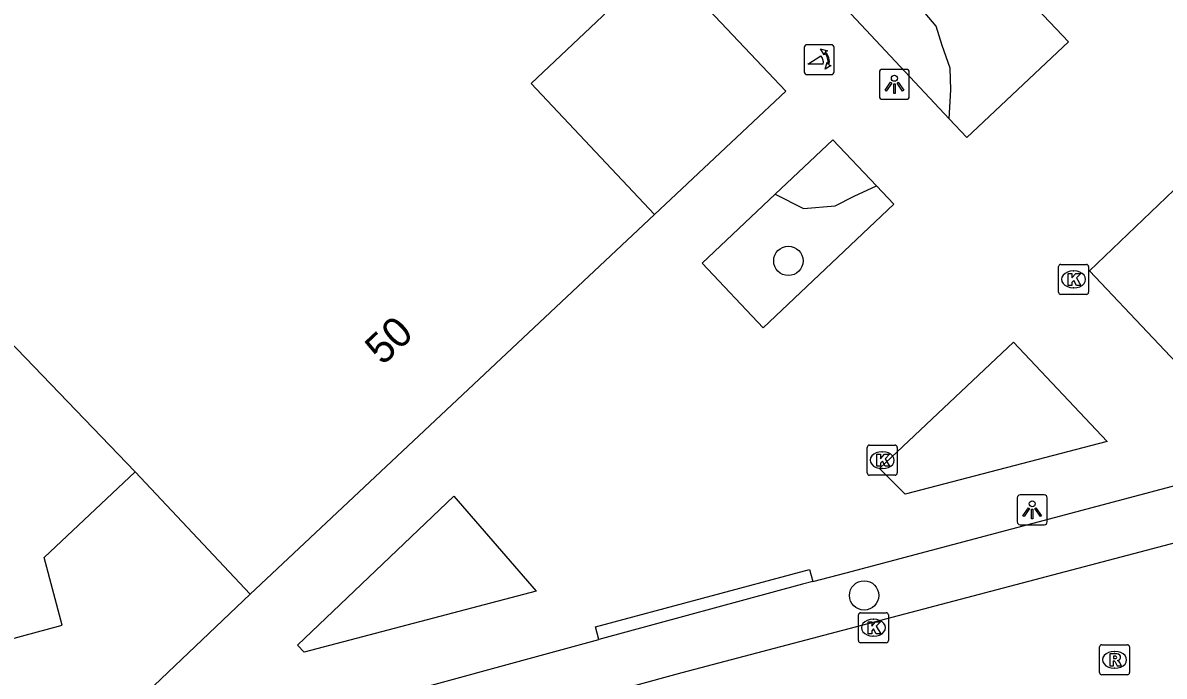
# Model space of a CAD drawing. Extents: x 162542 to 163144, y 380786 to 381511.
# Drawn here: x 162917.88 to 162955.91, y 381179.97 to 381201.72 of the extents above; entities that cross this region are included whole.
import ezdxf

# ---------------------------------------------------------------- set-up
doc = ezdxf.new("R2010")
doc.units = 0
for name, color, linetype in [('IMGEO_Boom', 7, 'Continuous'), ('IMGEO_Groenvoorziening', 7, 'Continuous'), ('IMGEO_Hek', 7, 'Continuous'), ('IMGEO_Kolk', 7, 'Continuous'), ('IMGEO_Lichtpunt', 7, 'Continuous'), ('IMGEO_Pand', 7, 'Continuous'), ('IMGEO_Pand_nummerreeks', 7, 'Continuous'), ('IMGEO_Poller', 7, 'Continuous'), ('IMGEO_Rijbaan_lokaal_open', 7, 'Continuous'), ('IMGEO_Rioolput', 7, 'Continuous'), ('IMGEO_Voetpad_open', 7, 'Continuous')]:
    doc.layers.add(name, color=color, linetype=linetype)

msp = doc.modelspace()

# ---------------------------------------------------------------- linework, layer by layer
at = {"layer": 'IMGEO_Boom'}
for centre in [(162943.384, 381193.797), (162945.909, 381182.656)]:
    msp.add_circle(centre, 0.489, dxfattribs=at)
at = {"layer": 'IMGEO_Groenvoorziening'}
for points in [[(162948.741, 381198.532), (162948.803, 381199.491), (162948.774, 381200.218), (162948.513, 381200.974), (162948.309, 381201.613), (162947.641, 381202.398), (162947.117, 381203.009), (162945.924, 381203.441)], [(162942.941, 381196.018), (162943.894, 381195.542), (162944.939, 381195.632), (162945.575, 381195.95), (162946.321, 381196.293)]]:
    msp.add_lwpolyline(points, dxfattribs=at)
at = {"layer": 'IMGEO_Hek'}
for points in [[(162943.3, 381199.444), (162939.164, 381203.82)], [(162938.919, 381195.337), (162943.3, 381199.444)]]:
    msp.add_lwpolyline(points, dxfattribs=at)
at = {"layer": 'IMGEO_Kolk'}
for p, q in [((162952.388, 381192.755), (162952.388, 381193.607)), ((162952.463, 381193.681), (162953.315, 381193.681)), ((162952.876, 381193.461), (162952.901, 381193.461)), ((162953.389, 381193.607), (162953.389, 381192.755)), ((162953.315, 381192.681), (162952.463, 381192.681)), ((162952.899, 381192.901), (162952.874, 381192.901)), ((162946.088, 381187.66), (162946.94, 381187.66)), ((162946.013, 381186.734), (162946.013, 381187.586)), ((162946.501, 381187.44), (162946.526, 381187.44)), ((162947.014, 381187.586), (162947.014, 381186.734)), ((162946.94, 381186.66), (162946.088, 381186.66)), ((162946.524, 381186.88), (162946.499, 381186.88)), ((162945.718, 381181.154), (162945.718, 381182.006)), ((162945.793, 381182.08), (162946.645, 381182.08)), ((162946.719, 381182.006), (162946.719, 381181.154)), ((162946.206, 381181.86), (162946.231, 381181.86)), ((162946.229, 381181.3), (162946.204, 381181.3)), ((162946.645, 381181.08), (162945.793, 381181.08))]:
    msp.add_line(p, q, dxfattribs=at)
for points in [[(162952.388, 381192.755), (162952.388, 381193.607)], [(162952.463, 381193.681), (162953.315, 381193.681)], [(162952.709, 381193.381), (162952.832, 381193.381), (162952.832, 381193.23), (162952.962, 381193.381), (162953.126, 381193.381), (162952.98, 381193.23), (162953.133, 381192.981), (162952.981, 381192.981), (162952.896, 381193.145), (162952.832, 381193.078), (162952.832, 381192.981), (162952.709, 381192.981), (162952.709, 381193.381)], [(162953.389, 381193.607), (162953.389, 381192.755)], [(162953.315, 381192.681), (162952.463, 381192.681)], [(162946.088, 381187.66), (162946.94, 381187.66)], [(162946.013, 381186.734), (162946.013, 381187.586)], [(162946.334, 381187.36), (162946.457, 381187.36), (162946.457, 381187.209), (162946.587, 381187.36), (162946.751, 381187.36), (162946.605, 381187.209), (162946.758, 381186.96), (162946.606, 381186.96), (162946.521, 381187.124), (162946.457, 381187.057), (162946.457, 381186.96), (162946.334, 381186.96), (162946.334, 381187.36)], [(162947.014, 381187.586), (162947.014, 381186.734)], [(162946.94, 381186.66), (162946.088, 381186.66)], [(162945.718, 381181.154), (162945.718, 381182.006)], [(162945.793, 381182.08), (162946.645, 381182.08)], [(162946.719, 381182.006), (162946.719, 381181.154)], [(162946.039, 381181.78), (162946.162, 381181.78), (162946.162, 381181.629), (162946.292, 381181.78), (162946.456, 381181.78), (162946.31, 381181.629), (162946.463, 381181.38), (162946.311, 381181.38), (162946.226, 381181.544), (162946.162, 381181.477), (162946.162, 381181.38), (162946.039, 381181.38), (162946.039, 381181.78)], [(162946.645, 381181.08), (162945.793, 381181.08)]]:
    msp.add_lwpolyline(points, dxfattribs=at)
for centre, start, end in [((162952.465, 381193.605), 91.552, 178.448), ((162952.465, 381193.605), 91.552, 178.448), ((162953.313, 381193.605), 1.552, 88.448), ((162953.313, 381193.605), 1.552, 88.448), ((162952.465, 381192.757), 181.552, 268.448), ((162952.465, 381192.757), 181.552, 268.448), ((162953.313, 381192.757), 271.552, 358.448), ((162953.313, 381192.757), 271.552, 358.448), ((162946.09, 381187.584), 91.552, 178.448), ((162946.09, 381187.584), 91.552, 178.448), ((162946.938, 381187.584), 1.552, 88.448), ((162946.938, 381187.584), 1.552, 88.448), ((162946.09, 381186.736), 181.552, 268.448), ((162946.09, 381186.736), 181.552, 268.448), ((162946.938, 381186.736), 271.552, 358.448), ((162946.938, 381186.736), 271.552, 358.448), ((162945.795, 381182.004), 91.552, 178.448), ((162945.795, 381182.004), 91.552, 178.448), ((162946.643, 381182.004), 1.552, 88.448), ((162946.643, 381182.004), 1.552, 88.448), ((162945.795, 381181.156), 181.552, 268.448), ((162945.795, 381181.156), 181.552, 268.448), ((162946.643, 381181.156), 271.552, 358.448), ((162946.643, 381181.156), 271.552, 358.448)]:
    msp.add_arc(centre, 0.0765, start, end, dxfattribs=at)
for centre, major_axis, ratio, start_param, end_param in [((162952.875, 381193.181), (-0.387, 0.002), 0.722429, 4.712389, 7.853982), ((162952.9, 381193.181), (-0.39, 0.002), 0.717154, 1.570796, 4.712389), ((162946.5, 381187.16), (-0.387, 0.002), 0.722429, 4.712389, 7.853982), ((162946.525, 381187.16), (-0.39, 0.002), 0.717154, 1.570796, 4.712389), ((162946.205, 381181.58), (-0.387, 0.002), 0.722429, 4.712389, 7.853982), ((162946.23, 381181.58), (-0.39, 0.002), 0.717154, 1.570796, 4.712389)]:
    msp.add_ellipse(centre, major_axis=major_axis, ratio=ratio, start_param=start_param, end_param=end_param, dxfattribs=at)
at = {"layer": 'IMGEO_Lichtpunt'}
for p, q in [((162946.418, 381200.08), (162946.418, 381199.273)), ((162946.418, 381200.08), (162946.418, 381199.273)), ((162947.32, 381200.175), (162946.512, 381200.175)), ((162947.32, 381200.175), (162946.512, 381200.175)), ((162947.414, 381199.273), (162947.414, 381200.08)), ((162947.414, 381199.273), (162947.414, 381200.08)), ((162946.512, 381199.179), (162947.32, 381199.179)), ((162946.512, 381199.179), (162947.32, 381199.179)), ((162951.011, 381185.909), (162951.011, 381185.102)), ((162951.011, 381185.909), (162951.011, 381185.102)), ((162951.913, 381186.004), (162951.105, 381186.004)), ((162951.913, 381186.004), (162951.105, 381186.004)), ((162952.007, 381185.102), (162952.007, 381185.909)), ((162952.007, 381185.102), (162952.007, 381185.909)), ((162951.105, 381185.008), (162951.913, 381185.008)), ((162951.105, 381185.008), (162951.913, 381185.008))]:
    msp.add_line(p, q, dxfattribs=at)
for points in [[(162946.792, 381199.744), (162946.831, 381199.716), (162946.643, 381199.454), (162946.605, 381199.481), (162946.792, 381199.744)], [(162946.894, 381199.696), (162946.941, 381199.696), (162946.941, 381199.374), (162946.894, 381199.374), (162946.894, 381199.696)], [(162947.004, 381199.716), (162947.042, 381199.743), (162947.229, 381199.481), (162947.19, 381199.453), (162947.004, 381199.716)], [(162951.385, 381185.573), (162951.424, 381185.545), (162951.236, 381185.283), (162951.198, 381185.31), (162951.385, 381185.573)], [(162951.487, 381185.525), (162951.534, 381185.525), (162951.534, 381185.203), (162951.487, 381185.203), (162951.487, 381185.525)], [(162951.597, 381185.545), (162951.635, 381185.572), (162951.822, 381185.31), (162951.783, 381185.282), (162951.597, 381185.545)]]:
    msp.add_lwpolyline(points, dxfattribs=at)
for centre in [(162946.917, 381199.878), (162951.51, 381185.707)]:
    msp.add_circle(centre, 0.0994, dxfattribs=at)
for centre, start, end in [((162946.512, 381200.08), 90, 180), ((162946.512, 381200.08), 90, 180), ((162947.32, 381200.08), 0, 90), ((162947.32, 381200.08), 0, 90), ((162946.512, 381199.273), 180, 270), ((162946.512, 381199.273), 180, 270), ((162947.32, 381199.273), 270, 0), ((162947.32, 381199.273), 270, 360), ((162951.105, 381185.909), 90, 180), ((162951.105, 381185.909), 90, 180), ((162951.913, 381185.909), 0, 90), ((162951.913, 381185.909), 0, 90), ((162951.105, 381185.102), 180, 270), ((162951.105, 381185.102), 180, 270), ((162951.913, 381185.102), 270, 0), ((162951.913, 381185.102), 270, 360)]:
    msp.add_arc(centre, 0.0946, start, end, dxfattribs=at)
at = {"layer": 'IMGEO_Pand'}
for points in [[(162938.919, 381195.337), (162934.812, 381199.7), (162939.164, 381203.82)], [(162938.919, 381195.337), (162930.161, 381187.114), (162925.455, 381182.694)], [(162917.122, 381191.446), (162921.624, 381186.774)], [(162913.342, 381180.093), (162919.187, 381181.662), (162918.59, 381183.913), (162921.624, 381186.774)], [(162921.624, 381186.774), (162925.455, 381182.694)]]:
    msp.add_lwpolyline(points, dxfattribs=at)
at = {"layer": 'IMGEO_Poller'}
for p, q in [((162944.815, 381200.997), (162944.007, 381200.997)), ((162944.815, 381200.997), (162944.007, 381200.997)), ((162943.913, 381200.902), (162943.913, 381200.095)), ((162943.913, 381200.902), (162943.913, 381200.095)), ((162944.909, 381200.095), (162944.909, 381200.902)), ((162944.909, 381200.095), (162944.909, 381200.902)), ((162944.007, 381200), (162944.815, 381200)), ((162944.007, 381200), (162944.815, 381200))]:
    msp.add_line(p, q, dxfattribs=at)
for points in [[(162944.548, 381200.353), (162944.035, 381200.353), (162944.465, 381200.628)], [(162944.592, 381200.726), (162944.58, 381200.653), (162944.455, 381200.858)], [(162944.455, 381200.858), (162944.686, 381200.792), (162944.615, 381200.76)], [(162944.608, 381200.181), (162944.674, 381200.412), (162944.704, 381200.344)], [(162944.74, 381200.317), (162944.812, 381200.306), (162944.608, 381200.181)]]:
    msp.add_lwpolyline(points, dxfattribs=at)
for centre, radius, start, end in [((162944.007, 381200.902), 0.0946, 90, 180), ((162944.007, 381200.902), 0.0946, 90, 180), ((162944.815, 381200.902), 0.0946, 0, 90), ((162944.815, 381200.902), 0.0946, 0, 90), ((162944.22, 381200.403), 0.332, 351.3247, 42.4854), ((162944.234, 381200.413), 0.476, 351.7527, 41.1691), ((162944.234, 381200.413), 0.516, 349.3569, 42.2912), ((162944.007, 381200.095), 0.0946, 180, 270), ((162944.007, 381200.095), 0.0946, 180, 270), ((162944.815, 381200.095), 0.0946, 270, 0), ((162944.815, 381200.095), 0.0946, 270, 0)]:
    msp.add_arc(centre, radius, start, end, dxfattribs=at)
at = {"layer": 'IMGEO_Rijbaan_lokaal_open'}
msp.add_lwpolyline([(163029.671, 381203.749), (162939.834, 381180.075), (162923.178, 381175.528)], dxfattribs=at)
at = {"layer": 'IMGEO_Rioolput'}
for p, q in [((162953.754, 381180.086), (162953.754, 381180.938)), ((162953.829, 381181.012), (162954.681, 381181.012)), ((162954.755, 381180.938), (162954.755, 381180.086)), ((162954.242, 381180.792), (162954.267, 381180.792)), ((162954.265, 381180.232), (162954.24, 381180.232)), ((162954.681, 381180.012), (162953.829, 381180.012))]:
    msp.add_line(p, q, dxfattribs=at)
for points in [[(162953.754, 381180.086), (162953.754, 381180.938)], [(162953.829, 381181.012), (162954.681, 381181.012)], [(162954.755, 381180.938), (162954.755, 381180.086)], [(162954.343, 381180.71), (162954.091, 381180.712), (162954.091, 381180.312)], [(162954.091, 381180.312), (162954.215, 381180.312), (162954.215, 381180.474), (162954.226, 381180.474)], [(162954.269, 381180.631), (162954.215, 381180.631), (162954.215, 381180.55)], [(162954.215, 381180.55), (162954.267, 381180.55)], [(162954.273, 381180.445), (162954.344, 381180.312), (162954.484, 381180.312), (162954.419, 381180.438)], [(162954.681, 381180.012), (162953.829, 381180.012)]]:
    msp.add_lwpolyline(points, dxfattribs=at)
for centre, radius, start, end in [((162953.831, 381180.936), 0.0765, 91.552, 178.448), ((162953.831, 381180.936), 0.0765, 91.552, 178.448), ((162954.679, 381180.936), 0.0765, 1.552, 88.448), ((162954.679, 381180.936), 0.0765, 1.552, 88.448), ((162954.225, 381180.421), 0.0533, 26.0293, 88.6989), ((162954.251, 381180.739), 0.19, 274.7715, 282.9687), ((162954.275, 381180.535), 0.0964, 77.0061, 93.1865), ((162954.289, 381180.592), 0.0378, 276.6634, 79.6772), ((162954.342, 381180.6), 0.109, 350.3612, 89.416), ((162954.34, 381180.6), 0.112, 277.5842, 350.9817), ((162954.324, 381180.385), 0.108, 29.5134, 73.7905), ((162953.831, 381180.088), 0.0765, 181.552, 268.448), ((162953.831, 381180.088), 0.0765, 181.552, 268.448), ((162954.679, 381180.088), 0.0765, 271.552, 358.448), ((162954.679, 381180.088), 0.0765, 271.552, 358.448)]:
    msp.add_arc(centre, radius, start, end, dxfattribs=at)
for centre, major_axis, ratio, start_param, end_param in [((162954.241, 381180.512), (-0.387, 0.002), 0.722429, 4.712389, 7.853982), ((162954.266, 381180.512), (-0.39, 0.002), 0.717154, 1.570796, 4.712389)]:
    msp.add_ellipse(centre, major_axis=major_axis, ratio=ratio, start_param=start_param, end_param=end_param, dxfattribs=at)
at = {"layer": 'IMGEO_Voetpad_open'}
for points in [[(162948.336, 381205.724), (162952.72, 381201.096), (162949.331, 381197.901), (162948.741, 381198.532)], [(162939.164, 381203.82), (162943.3, 381199.444), (162938.919, 381195.337)], [(162948.741, 381198.532), (162944.983, 381202.551)], [(162942.941, 381196.018), (162944.864, 381197.833), (162946.321, 381196.293)], [(162956.739, 381196.635), (162961.012, 381192.127), (162957.656, 381188.976), (162953.416, 381193.464), (162956.739, 381196.635)], [(162946.321, 381196.293), (162946.898, 381195.683), (162942.545, 381191.565), (162940.51, 381193.725), (162942.941, 381196.018)], [(162946.421, 381186.882), (162950.882, 381191.089), (162954.012, 381187.786), (162947.274, 381186.026), (162946.421, 381186.882)], [(162944.204, 381183.118), (162945.307, 381183.409), (162968.263, 381189.504)], [(162932.236, 381185.965), (162934.984, 381182.801), (162927.248, 381180.762), (162927.031, 381181), (162932.236, 381185.965)], [(162937.074, 381181.191), (162936.958, 381181.61), (162944.091, 381183.522), (162944.204, 381183.118)], [(162944.204, 381183.118), (162943.854, 381183.025), (162937.074, 381181.191)], [(162925.455, 381182.694), (162921.793, 381179.222), (162849.909, 381160.144)], [(162920.542, 381176.676), (162937.074, 381181.191)]]:
    msp.add_lwpolyline(points, dxfattribs=at)

# ---------------------------------------------------------------- texts
at = {"layer": 'IMGEO_Pand_nummerreeks'}
msp.add_text('50', height=1, rotation=43.201, dxfattribs=at).set_placement((162929.864, 381190.291))

doc.saveas('drawing.dxf')
